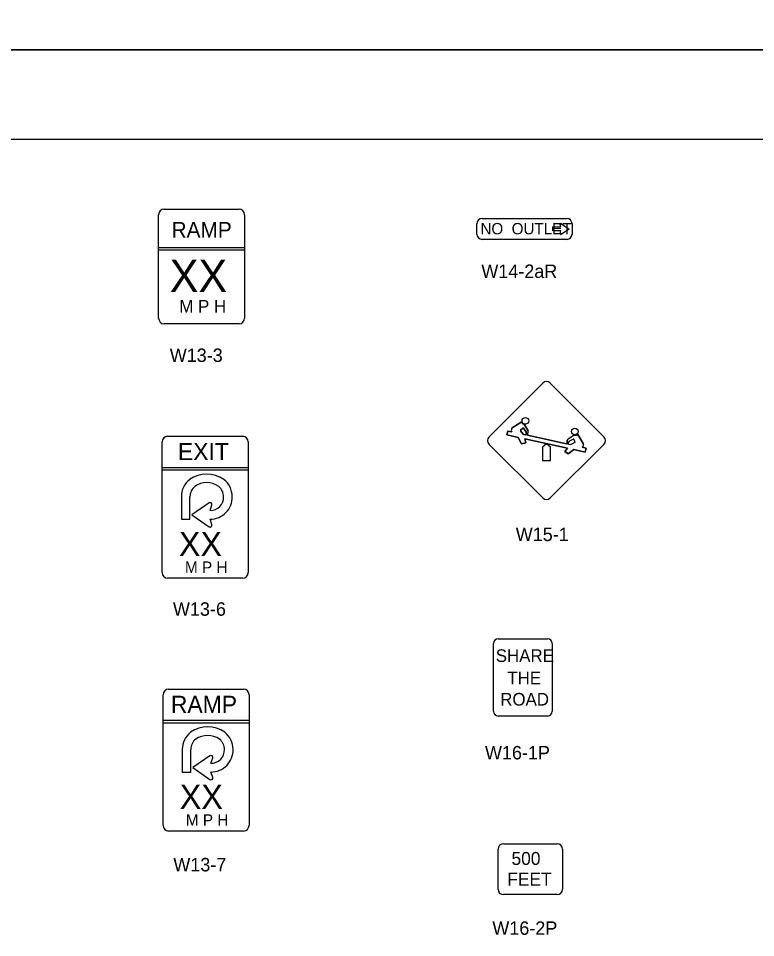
# Model space of a CAD drawing. Extents: x 42133 to 45533, y 41351 to 47951.
# Drawn here: x 44232 to 44644, y 46356 to 46869 of the extents above; entities that cross this region are included whole.
import ezdxf

# ---------------------------------------------------------------- set-up
doc = ezdxf.new("R2010")
doc.units = 0
for name, color, linetype in [('#plot_shape', 7, 'Continuous'), ('P_ODOT_PLAN_Border', 7, 'Continuous'), ('P_TRAF_SIGN_SignDetails', 7, 'Continuous')]:
    doc.layers.add(name, color=color, linetype=linetype)

msp = doc.modelspace()

# ---------------------------------------------------------------- linework, layer by layer
at = {"layer": '#plot_shape'}
for points in [[(43833.34, 46851.35), (45533.34, 46851.35), (45533.34, 47951.35), (43833.34, 47951.35)], [(43833.34, 45751.35), (45533.34, 45751.35), (45533.34, 46851.35), (43833.34, 46851.35)]]:
    msp.add_lwpolyline(points, close=True, dxfattribs=at)
at = {"layer": 'P_ODOT_PLAN_Border'}
msp.add_lwpolyline([(43908.34, 45801.35), (45508.34, 45801.35), (45508.34, 46801.35), (43908.34, 46801.35)], close=True, dxfattribs=at)
at = {"layer": 'P_TRAF_SIGN_SignDetails'}
for p, q in [((44313.6, 46762.47), (44355.57, 46762.47)), ((44310.6, 46701.7), (44310.6, 46759.28)), ((44358.57, 46759.28), (44358.57, 46701.7)), ((44491.24, 46757.32), (44538.36, 46757.32)), ((44488.24, 46748.6), (44488.24, 46754.33)), ((44541.34, 46754.33), (44541.34, 46748.6)), ((44538.36, 46745.6), (44491.24, 46745.6)), ((44310.6, 46741.17), (44358.57, 46741.17)), ((44310.6, 46739.84), (44358.57, 46739.84)), ((44355.57, 46698.51), (44313.6, 46698.51)), ((44495.08, 46635.5), (44524.96, 46665.38)), ((44529.22, 46665.38), (44559.1, 46635.5)), ((44312.61, 46559.71), (44312.61, 46632.57)), ((44315.61, 46635.77), (44357.58, 46635.77)), ((44360.58, 46632.57), (44360.58, 46559.71)), ((44495.08, 46631.24), (44524.96, 46601.37)), ((44559.1, 46631.24), (44529.22, 46601.36)), ((44312.61, 46618.32), (44360.58, 46618.32)), ((44312.61, 46616.99), (44360.58, 46616.99)), ((44357.58, 46556.52), (44315.61, 46556.52)), ((44497.51, 46482.33), (44497.51, 46520.11)), ((44500.2, 46522.8), (44527.63, 46522.8)), ((44530.33, 46520.11), (44530.33, 46482.33)), ((44316.1, 46494.69), (44358.06, 46494.69)), ((44313.1, 46418.63), (44313.1, 46491.49)), ((44361.06, 46491.49), (44361.06, 46418.63)), ((44527.63, 46479.64), (44500.2, 46479.64)), ((44313.1, 46477.24), (44361.06, 46477.24)), ((44313.1, 46475.91), (44361.06, 46475.91)), ((44358.06, 46415.44), (44316.1, 46415.44)), ((44503.06, 46408.37), (44533, 46408.37)), ((44500.06, 46382.95), (44500.06, 46405.37)), ((44535.99, 46405.37), (44535.99, 46382.95)), ((44533, 46379.95), (44503.06, 46379.95))]:
    msp.add_line(p, q, dxfattribs=at)
for points in [[(44530.67, 46750.29), (44530.67, 46752.52), (44535.15, 46752.52), (44534.74, 46753.84)], [(44530.67, 46750.29), (44530.67, 46752.52), (44535.15, 46752.52), (44534.74, 46753.84)], [(44530.67, 46750.29), (44530.67, 46752.52), (44535.15, 46752.52), (44534.74, 46753.84)], [(44535.4, 46754.33), (44539.67, 46751.4), (44535.4, 46748.48)], [(44535.4, 46754.33), (44539.67, 46751.4), (44535.4, 46748.48)], [(44535.4, 46754.33), (44539.67, 46751.4), (44535.4, 46748.48)], [(44534.74, 46748.96), (44535.15, 46750.29), (44530.67, 46750.29)], [(44534.74, 46748.96), (44535.15, 46750.29), (44530.67, 46750.29)], [(44534.74, 46748.96), (44535.15, 46750.29), (44530.67, 46750.29)], [(44507.99, 46640.42), (44512.86, 46643.68), (44514.79, 46642.16), (44516.85, 46638.82)], [(44516.85, 46638.82), (44514.79, 46642.16), (44512.86, 46643.68), (44507.99, 46640.42)], [(44516.85, 46638.82), (44514.79, 46642.16), (44512.86, 46643.68), (44507.99, 46640.42)], [(44511.34, 46635.12), (44504.99, 46636.51), (44505.47, 46638.68), (44507.77, 46638.18)], [(44507.77, 46638.18), (44505.47, 46638.68), (44504.99, 46636.51), (44511.34, 46635.12)], [(44507.77, 46638.18), (44505.47, 46638.68), (44504.99, 46636.51), (44511.34, 46635.12)], [(44512.65, 46638.79), (44514.34, 46636.74), (44515.51, 46636.48)], [(44542.82, 46632.21), (44540.38, 46631.05), (44539.13, 46631.32), (44539.21, 46631.53), (44538.43, 46631.7), (44538.33, 46631.5), (44516.44, 46636.28), (44516.44, 46636.51), (44515.6, 46636.69), (44515.51, 46636.48), (44514.34, 46636.74), (44512.65, 46638.79)], [(44542.82, 46632.21), (44540.38, 46631.05), (44539.13, 46631.32), (44539.21, 46631.53), (44538.43, 46631.7), (44538.33, 46631.5), (44516.44, 46636.28), (44516.44, 46636.51), (44515.6, 46636.69), (44515.51, 46636.48), (44514.34, 46636.74), (44512.65, 46638.79)], [(44513.86, 46640.29), (44512.66, 46639.09)], [(44512.66, 46639.09), (44513.86, 46640.29)], [(44512.66, 46639.09), (44513.86, 46640.29)], [(44515.64, 46638.47), (44514.2, 46640.27)], [(44514.2, 46640.27), (44515.64, 46638.47)], [(44514.2, 46640.27), (44515.64, 46638.47)], [(44515.69, 46637.05), (44515.69, 46638.33)], [(44515.69, 46638.33), (44515.69, 46637.05)], [(44515.69, 46638.33), (44515.69, 46637.05)], [(44546.98, 46629.61), (44549.2, 46629.12), (44548.72, 46626.95), (44542.4, 46628.33), (44539.17, 46625.88), (44537.34, 46627.26), (44538.8, 46629.12), (44514.92, 46634.34), (44515.49, 46632.16), (44513.21, 46631.44), (44511.34, 46635.12)], [(44511.34, 46635.12), (44513.21, 46631.44), (44515.49, 46632.16), (44514.92, 46634.34), (44538.8, 46629.12), (44537.34, 46627.26), (44539.17, 46625.88), (44542.4, 46628.33), (44548.72, 46626.95), (44549.2, 46629.12), (44546.98, 46629.61)], [(44511.34, 46635.12), (44513.21, 46631.44), (44515.49, 46632.16), (44514.92, 46634.34), (44538.8, 46629.12), (44537.34, 46627.26), (44539.17, 46625.88), (44542.4, 46628.33), (44548.72, 46626.95), (44549.2, 46629.12), (44546.98, 46629.61)], [(44515.51, 46636.48), (44515.64, 46636.79)], [(44515.64, 46636.79), (44515.6, 46636.7), (44516.44, 46636.51), (44516.44, 46637.41)], [(44515.64, 46636.79), (44515.6, 46636.7), (44516.44, 46636.51), (44516.44, 46637.41)], [(44516.44, 46637.41), (44516.44, 46636.28), (44538.33, 46631.5), (44538.67, 46632.18)], [(44538.67, 46632.18), (44538.43, 46631.71), (44539.21, 46631.54), (44539.73, 46632.97)], [(44538.67, 46632.18), (44538.43, 46631.71), (44539.21, 46631.54), (44539.73, 46632.97)], [(44538.7, 46632.28), (44538.7, 46633.63)], [(44538.7, 46633.63), (44538.7, 46632.28)], [(44538.7, 46633.63), (44538.7, 46632.28)], [(44542.82, 46632.21), (44540.38, 46631.05), (44539.13, 46631.32), (44539.73, 46632.97)], [(44539.83, 46633.09), (44541.96, 46634.17)], [(44539.83, 46633.09), (44541.96, 46634.17)], [(44539.83, 46633.09), (44541.96, 46634.17)], [(44542.26, 46634.05), (44542.93, 46632.5)], [(44542.26, 46634.05), (44542.93, 46632.5)], [(44542.26, 46634.05), (44542.93, 46632.5)], [(44544.63, 46636.68), (44547.62, 46631.77)], [(44547.62, 46631.77), (44544.63, 46636.68)], [(44547.62, 46631.77), (44544.63, 46636.68)], [(44323.28, 46602.08), (44323.28, 46589.44), (44328.09, 46589.44), (44328.09, 46602.08)], [(44323.28, 46602.08), (44323.28, 46589.44), (44328.09, 46589.44), (44328.09, 46602.08)], [(44323.28, 46602.08), (44323.28, 46589.44), (44328.09, 46589.44), (44328.09, 46602.08)], [(44338.75, 46598.56), (44329.14, 46591.92), (44338.75, 46585.29)], [(44338.75, 46598.56), (44329.14, 46591.92), (44338.75, 46585.29)], [(44338.75, 46598.56), (44329.14, 46591.92), (44338.75, 46585.29)], [(44339.32, 46594.37), (44340.29, 46597.41)], [(44339.32, 46594.37), (44340.29, 46597.41)], [(44339.32, 46594.37), (44340.29, 46597.41)], [(44340.29, 46586.44), (44339.32, 46589.47), (44339.32, 46589.47)], [(44340.29, 46586.44), (44339.32, 46589.47), (44339.32, 46589.47)], [(44340.29, 46586.44), (44339.32, 46589.47), (44339.32, 46589.47)], [(44323.76, 46461), (44323.76, 46448.36), (44328.58, 46448.36), (44328.58, 46461)], [(44323.76, 46461), (44323.76, 46448.36), (44328.58, 46448.36), (44328.58, 46461)], [(44323.76, 46461), (44323.76, 46448.36), (44328.58, 46448.36), (44328.58, 46461)], [(44339.23, 46457.48), (44329.63, 46450.85), (44339.23, 46444.21)], [(44339.23, 46457.48), (44329.63, 46450.85), (44339.23, 46444.21)], [(44339.23, 46457.48), (44329.63, 46450.85), (44339.23, 46444.21)], [(44339.81, 46453.3), (44340.78, 46456.33)], [(44339.81, 46453.3), (44340.78, 46456.33)], [(44339.81, 46453.3), (44340.78, 46456.33)], [(44340.78, 46445.36), (44339.81, 46448.4), (44339.81, 46448.4)], [(44340.78, 46445.36), (44339.81, 46448.4), (44339.81, 46448.4)], [(44340.78, 46445.36), (44339.81, 46448.4), (44339.81, 46448.4)]]:
    msp.add_lwpolyline(points, dxfattribs=at)
for points in [[(44529.36, 46622.23), (44529.36, 46629.61), (44527.14, 46631.61), (44524.92, 46629.61), (44524.92, 46622.23)], [(44524.92, 46629.61), (44524.92, 46622.23), (44529.36, 46622.23), (44529.36, 46629.61), (44527.14, 46631.61)], [(44524.92, 46629.61), (44524.92, 46622.23), (44529.36, 46622.23), (44529.36, 46629.61), (44527.14, 46631.61)]]:
    msp.add_lwpolyline(points, close=True, dxfattribs=at)
for centre in [(44515.29, 46644.37), (44515.29, 46644.37), (44515.29, 46644.37), (44542.93, 46638.45), (44542.93, 46638.45), (44542.93, 46638.45)]:
    msp.add_circle(centre, 1.86, dxfattribs=at)
for centre, radius, start, end in [((44491.24, 46754.33), 2.99, 90, 180), ((44538.36, 46754.33), 2.99, 360, 90), ((44535.15, 46753.97), 0.433, 55.6003, 197.0573), ((44535.15, 46753.97), 0.433, 55.6003, 197.0573), ((44535.15, 46753.97), 0.433, 55.6003, 197.0573), ((44491.24, 46748.6), 2.99, 180, 270), ((44535.15, 46748.84), 0.433, 162.9427, 304.3997), ((44535.15, 46748.84), 0.433, 162.9427, 304.3997), ((44535.15, 46748.84), 0.433, 162.9427, 304.3997), ((44538.36, 46748.6), 2.99, 270, 360), ((44527.09, 46663.24), 3.01, 45, 135), ((44509.29, 46639.23), 1.84, 158.8297, 214.6569), ((44509.29, 46639.23), 1.84, 158.8297, 214.6569), ((44509.29, 46639.23), 1.84, 158.8297, 214.6569), ((44508.61, 46639.49), 1.12, 123.8431, 158.8297), ((44508.61, 46639.49), 1.12, 123.8431, 158.8297), ((44508.61, 46639.49), 1.12, 123.8431, 158.8297), ((44512.82, 46638.93), 0.224, 135.0173, 219.5878), ((44512.82, 46638.93), 0.224, 135.0173, 219.5878), ((44512.82, 46638.93), 0.224, 135.0173, 219.5878), ((44514.02, 46640.13), 0.224, 38.6609, 135.0173), ((44514.02, 46640.13), 0.224, 38.6609, 135.0173), ((44514.02, 46640.13), 0.224, 38.6609, 135.0173), ((44515.47, 46638.33), 0.224, 0, 38.6609), ((44515.47, 46638.33), 0.224, 360, 38.6609), ((44515.47, 46638.33), 0.224, 360, 38.6609), ((44516.55, 46637.41), 0.112, 129.4978, 180), ((44516.55, 46637.41), 0.112, 129.4978, 180), ((44516.55, 46637.41), 0.112, 129.4978, 180), ((44515.66, 46638.49), 1.29, 309.4978, 358.6942), ((44515.66, 46638.49), 1.29, 309.4978, 358.6942), ((44515.66, 46638.49), 1.29, 309.4978, 358.6942), ((44516.27, 46638.47), 0.673, 358.6942, 31.6369), ((44516.27, 46638.47), 0.673, 358.6942, 31.6369), ((44516.27, 46638.47), 0.673, 358.6942, 31.6369), ((44497.22, 46633.37), 3.01, 135, 225), ((44515.02, 46637.05), 0.673, 337.343, 360), ((44515.02, 46637.05), 0.673, 337.343, 0), ((44515.02, 46637.05), 0.673, 337.343, 0), ((44538.92, 46633.63), 0.224, 127.1818, 180), ((44538.92, 46633.63), 0.224, 127.1818, 180), ((44538.92, 46633.63), 0.224, 127.1818, 180), ((44564.94, 46599.33), 43.28, 121.1968, 127.1818), ((44564.94, 46599.33), 43.28, 121.1968, 127.1818), ((44564.94, 46599.33), 43.28, 121.1968, 127.1818), ((44539.94, 46632.89), 0.224, 116.884, 160.0339), ((44539.94, 46632.89), 0.224, 116.884, 160.0339), ((44539.94, 46632.89), 0.224, 116.884, 160.0339), ((44542.06, 46633.97), 0.224, 23.1675, 116.884), ((44542.06, 46633.97), 0.224, 23.1675, 116.884), ((44542.06, 46633.97), 0.224, 23.1675, 116.884), ((44542.3, 46644.73), 8.39, 271.5179, 286.1694), ((44542.3, 46644.73), 8.39, 271.5179, 286.1694), ((44542.3, 46644.73), 8.39, 271.5179, 286.1694), ((44542.72, 46632.41), 0.224, 295.4224, 23.1675), ((44542.72, 46632.41), 0.224, 295.4224, 23.1675), ((44542.72, 46632.41), 0.224, 295.4224, 23.1675), ((44556.97, 46633.37), 3.01, 315, 45), ((44538.47, 46632.28), 0.224, 333.2853, 360), ((44538.47, 46632.28), 0.224, 333.2853, 360), ((44538.47, 46632.28), 0.224, 333.2853, 360), ((44545.89, 46631.16), 1.9, 305.169, 2.3208), ((44545.89, 46631.16), 1.9, 305.169, 2.3208), ((44545.89, 46631.16), 1.9, 305.169, 2.3208), ((44546.67, 46631.19), 1.12, 2.3208, 31.3714), ((44546.67, 46631.19), 1.12, 2.3208, 31.3714), ((44546.67, 46631.19), 1.12, 2.3208, 31.3714), ((44337.47, 46598.22), 16.46, 54.5604, 125.4396), ((44337.47, 46598.22), 16.46, 54.5604, 125.4396), ((44337.47, 46598.22), 16.46, 54.5604, 125.4396), ((44335.39, 46602.08), 12.11, 127.9974, 180), ((44335.39, 46602.08), 12.11, 127.9974, 180), ((44335.39, 46602.08), 12.11, 127.9974, 180), ((44335.39, 46602.08), 7.29, 128.8079, 180), ((44335.39, 46602.08), 7.29, 128.8079, 180), ((44335.39, 46602.08), 7.29, 128.8079, 180), ((44337.47, 46598.22), 11.64, 55.1108, 124.8892), ((44337.47, 46598.22), 11.64, 55.1108, 124.8892), ((44337.47, 46598.22), 11.64, 55.1108, 124.8892), ((44339.56, 46602.08), 7.29, 359.5724, 51.1921), ((44339.56, 46602.08), 7.29, 359.5724, 51.1921), ((44339.56, 46602.08), 7.29, 359.5724, 51.1921), ((44339.56, 46602.08), 12.11, 0, 52.0026), ((44339.56, 46602.08), 12.11, 0, 52.0026), ((44339.56, 46602.08), 12.11, 0, 52.0026), ((44339.35, 46601.8), 12.33, 269.896, 1.2992), ((44339.35, 46601.8), 12.33, 269.896, 1.2992), ((44339.35, 46601.8), 12.33, 269.896, 1.2992), ((44339.54, 46601.69), 7.32, 268.2881, 2.6238), ((44339.54, 46601.69), 7.32, 268.2881, 2.6238), ((44339.54, 46601.69), 7.32, 268.2881, 2.6238), ((44339.32, 46597.72), 1.02, 342.2718, 124.6386), ((44339.32, 46597.72), 1.02, 342.2718, 124.6386), ((44339.32, 46597.72), 1.02, 342.2718, 124.6386), ((44527.09, 46603.49), 3.01, 225, 315), ((44339.32, 46586.13), 1.02, 235.3614, 17.7282), ((44339.32, 46586.13), 1.02, 235.3614, 17.7282), ((44339.32, 46586.13), 1.02, 235.3614, 17.7282), ((44500.2, 46520.11), 2.69, 90, 180), ((44527.63, 46520.11), 2.69, 0, 90), ((44500.2, 46482.33), 2.69, 180, 270), ((44527.63, 46482.33), 2.69, 270, 360), ((44337.96, 46457.14), 16.46, 54.5604, 125.4396), ((44337.96, 46457.14), 16.46, 54.5604, 125.4396), ((44337.96, 46457.14), 16.46, 54.5604, 125.4396), ((44335.87, 46461), 12.11, 127.9974, 180), ((44335.87, 46461), 12.11, 127.9974, 180), ((44335.87, 46461), 12.11, 127.9974, 180), ((44337.96, 46457.14), 11.64, 55.1108, 124.8892), ((44337.96, 46457.14), 11.64, 55.1108, 124.8892), ((44337.96, 46457.14), 11.64, 55.1108, 124.8892), ((44340.05, 46461), 12.11, 0, 52.0026), ((44340.05, 46461), 12.11, 0, 52.0026), ((44340.05, 46461), 12.11, 0, 52.0026), ((44335.87, 46461), 7.29, 128.8079, 180), ((44335.87, 46461), 7.29, 128.8079, 180), ((44335.87, 46461), 7.29, 128.8079, 180), ((44340.05, 46461), 7.29, 359.5724, 51.1921), ((44340.05, 46461), 7.29, 359.5724, 51.1921), ((44340.05, 46461), 7.29, 359.5724, 51.1921), ((44339.83, 46460.72), 12.33, 269.896, 1.2992), ((44339.83, 46460.72), 12.33, 269.896, 1.2992), ((44339.83, 46460.72), 12.33, 269.896, 1.2992), ((44340.03, 46460.61), 7.32, 268.2881, 2.6238), ((44340.03, 46460.61), 7.32, 268.2881, 2.6238), ((44340.03, 46460.61), 7.32, 268.2881, 2.6238), ((44339.81, 46456.64), 1.02, 342.2718, 124.6386), ((44339.81, 46456.64), 1.02, 342.2718, 124.6386), ((44339.81, 46456.64), 1.02, 342.2718, 124.6386), ((44339.81, 46445.05), 1.02, 235.3614, 17.7282), ((44339.81, 46445.05), 1.02, 235.3614, 17.7282), ((44339.81, 46445.05), 1.02, 235.3614, 17.7282), ((44503.06, 46405.37), 2.99, 90, 180), ((44532.99, 46405.37), 2.99, 360, 90), ((44503.06, 46382.94), 2.99, 180, 270), ((44533, 46382.94), 2.99, 270, 360)]:
    msp.add_arc(centre, radius, start, end, dxfattribs=at)
for centre, major_axis, start_param, end_param in [((44313.61, 46759.28), (0, 3.2), 0, 1.570796), ((44355.57, 46759.28), (0, 3.2), 4.712389, 6.283185), ((44313.61, 46701.71), (0, -3.2), 4.712389, 6.283185), ((44355.57, 46701.71), (0, 3.2), 3.141593, 4.712389), ((44315.61, 46632.57), (0, 3.2), 0, 1.570796), ((44357.57, 46632.57), (0, 3.2), 4.712389, 6.283185), ((44315.61, 46559.71), (0, -3.2), 4.712389, 6.283185), ((44357.57, 46559.71), (0, 3.2), 3.141593, 4.712389), ((44316.1, 46491.49), (0, 3.2), 0, 1.570796), ((44358.06, 46491.49), (0, 3.2), 4.712389, 6.283185), ((44316.1, 46418.63), (0, -3.2), 4.712389, 6.283185), ((44358.06, 46418.63), (0, 3.2), 3.141593, 4.712389)]:
    msp.add_ellipse(centre, major_axis=major_axis, ratio=0.9371, start_param=start_param, end_param=end_param, dxfattribs=at)

# ---------------------------------------------------------------- texts
for s, height, p in [('RAMP', 8.699, (44317.8, 46746.63)), ('NO  OUTLET', 6.335, (44490.23, 46748.43)), ('XX', 17.955, (44316.81, 46716.25)), ('W14-2aR', 7.5, (44490.74, 46724.08)), ('M P H', 7.036, (44322.16, 46704.75)), ('W13-3', 7.5, (44316.83, 46677.21)), ('EXIT', 9.569, (44321.37, 46622.44)), ('XX', 13.49, (44321.9, 46568.91)), ('W15-1', 7.5, (44509.95, 46577.25)), ('M P H', 6.396, (44325.3, 46559.48)), ('W13-6', 7.5, (44318.61, 46535.59)), ('SHARE', 7.046, (44498.77, 46509.81)), ('THE', 7.046, (44505.23, 46497.35)), ('RAMP', 9.569, (44317.42, 46481.36)), ('ROAD', 7.046, (44501.26, 46485.48)), ('W16-1P', 7.5, (44492.77, 46455.42)), ('XX', 13.49, (44322.39, 46427.83)), ('M P H', 6.396, (44325.79, 46418.41)), ('500', 7.245, (44507.56, 46396.52)), ('W13-7', 7.5, (44318.83, 46392.93)), ('FEET', 7.245, (44505.19, 46384.97)), ('W16-2P', 7.5, (44496.88, 46357.54))]:
    msp.add_text(s, height=height, dxfattribs=at).set_placement(p)

doc.saveas('drawing.dxf')
